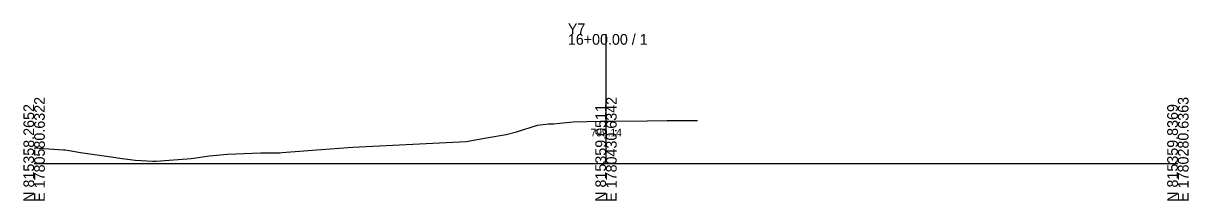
# Model space of a CAD drawing. Extents: x -26 to 2903, y -10 to 5536.
# Drawn here: x 1297.2 to 1602.8, y -9.7 to 36.8 of the extents above; entities that cross this region are included whole.
import ezdxf

# ---------------------------------------------------------------- set-up
doc = ezdxf.new("R2010")
doc.units = 0
for name, color, linetype in [('Exist Cross Section Cell', 7, 'Continuous'), ('Exist XS Center Line Elevation Label', 7, 'Continuous'), ('Exist XS Ground Line', 7, 'Continuous')]:
    doc.layers.add(name, color=color, linetype=linetype)

msp = doc.modelspace()

# ---------------------------------------------------------------- linework, layer by layer
at = {"layer": 'Exist Cross Section Cell'}
for p, q in [((1450, 0), (1450, 33.95)), ((1300, 0), (1450, 0)), ((1450, 0), (1600, 0))]:
    msp.add_line(p, q, dxfattribs=at)
at = {"layer": 'Exist XS Ground Line'}
for p, q in [((1426.5, 8.36), (1432.03, 10.12)), ((1432.03, 10.12), (1434.93, 10.4)), ((1434.93, 10.4), (1436.22, 10.44)), ((1436.22, 10.44), (1437.89, 10.64)), ((1437.89, 10.64), (1441.37, 10.92)), ((1441.37, 10.92), (1448.56, 11.11)), ((1448.56, 11.11), (1449.96, 11.14)), ((1449.96, 11.14), (1451.55, 11.16)), ((1451.55, 11.16), (1460.82, 11.25)), ((1460.82, 11.25), (1466.03, 11.3)), ((1466.03, 11.3), (1469.48, 11.32)), ((1469.48, 11.32), (1474.01, 11.32)), ((1413.29, 5.84), (1418.66, 6.76)), ((1418.66, 6.76), (1423.82, 7.6)), ((1423.82, 7.6), (1426.5, 8.36)), ((1300, 4.18), (1307.7, 3.62)), ((1307.7, 3.62), (1308.1, 3.58)), ((1308.1, 3.58), (1309.19, 3.41)), ((1309.19, 3.41), (1312.16, 2.92)), ((1365, 2.89), (1377.64, 3.9)), ((1377.64, 3.9), (1383.62, 4.3)), ((1383.62, 4.3), (1408.11, 5.5)), ((1408.11, 5.5), (1413.29, 5.84)), ((1312.16, 2.92), (1320.84, 1.67)), ((1320.84, 1.67), (1321.43, 1.59)), ((1321.43, 1.59), (1321.77, 1.55)), ((1321.77, 1.55), (1326.52, 0.95)), ((1326.52, 0.95), (1331.09, 0.63)), ((1331.09, 0.63), (1331.56, 0.61)), ((1331.56, 0.61), (1331.99, 0.64)), ((1331.99, 0.64), (1341.2, 1.35)), ((1341.2, 1.35), (1346.03, 2.07)), ((1346.03, 2.07), (1350.73, 2.45)), ((1350.73, 2.45), (1359.45, 2.8)), ((1359.45, 2.8), (1364.43, 2.87)), ((1364.43, 2.87), (1365, 2.89))]:
    msp.add_line(p, q, dxfattribs=at)

# ---------------------------------------------------------------- texts
at = {"layer": 'Exist Cross Section Cell'}
for s, p in [('Y7', (1440, 33.95)), ('16+00.00 / 1', (1440, 31.15))]:
    msp.add_text(s, height=2.8, dxfattribs=at).set_placement(p)
for s, p in [('N 815358.2652', (1300, -10)), ('E 1780580.6322', (1302.8, -10)), ('N 815359.0511', (1450, -10)), ('E 1780430.6342', (1452.8, -10)), ('N 815359.8369', (1600, -10)), ('E 1780280.6363', (1602.8, -10))]:
    msp.add_text(s, height=2.8, rotation=90, dxfattribs=at).set_placement(p)
at = {"layer": 'Exist XS Center Line Elevation Label'}
msp.add_text('799.14', height=2, dxfattribs=at).set_placement((1445.96, 7.14))

doc.saveas('drawing.dxf')
